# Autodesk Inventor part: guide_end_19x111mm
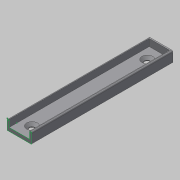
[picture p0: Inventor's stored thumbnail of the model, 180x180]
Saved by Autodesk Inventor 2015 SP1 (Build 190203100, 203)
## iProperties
Created: 2015-06
Part Number: guide_end_19x111mm
Material: Generic
Document SubType Name: Modeling
Designer: uidn2323
Density: 1 g/cm^3
Appearance: Default
Author: uidn2323
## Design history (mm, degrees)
derived "lyžina.ipt"
  sketch "Sketch1"
    geometry: L1 (0, 0)-(-19, 0) reference; L2 (-19, 0)-(-19, 7) reference; L3 (0, 7)-(0, 0) reference; L4 (-1.5, 2.5)-(-17.5, 2.5) reference; L5 (-17.5, 2.5)-(-17.5, 8) reference; L6 (-1.5, 8)-(-1.5, 2.5) reference; L7 (-18, 8)-(-17.5, 8) reference; L8 (-1.5, 8)-(-1, 8) reference; A1 r 1 centre (-1, 7) between (0, 7) and (-1, 8) reference; A2 r 1 centre (-18, 7) between (-18, 8) and (-19, 7) reference; 3 further points
  sketch "Sketch2"
    geometry: L1 (-16, -110)-(0, -110) reference; L2 (-16, 0)-(0, 0) reference; L3 (0, 0)-(0, -110) reference; C1 r 2.25 at (-8, -100.5) reference; C2 r 2.25 at (-8, -10) reference; 1 further point
feature "Solid1::lyžina.ipt" dims "d0" = 10
tag "TaggingFeature1"
body "Solid1"
